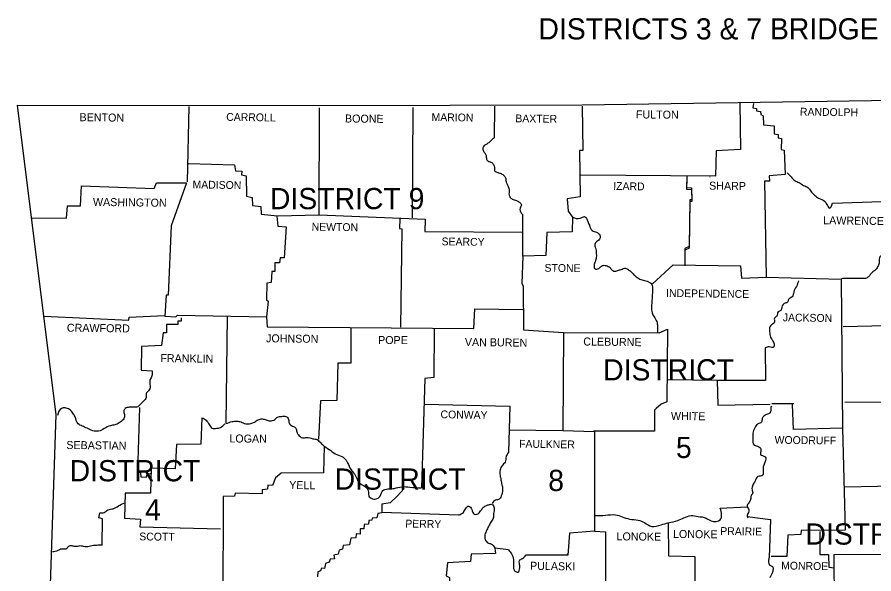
# Model space of a CAD drawing. Extents: x -43543 to 34500, y -13675 to 11152.
# Drawn here: x 10765 to 15268, y 7833 to 10759 of the extents above; entities that cross this region are included whole.
import ezdxf

# ---------------------------------------------------------------- set-up
doc = ezdxf.new("R2010")
doc.units = 0
for name, color, linetype in [('1', 7, 'Continuous'), ('2', 7, 'Continuous'), ('3', 7, 'Continuous'), ('R_Border', 7, 'Continuous')]:
    doc.layers.add(name, color=color, linetype=linetype)

msp = doc.modelspace()

# ---------------------------------------------------------------- linework, layer by layer
at = {"layer": '1'}
msp.add_line((14731.5, 8728.9), (14848, 8728.9), dxfattribs=at)
for points in [[(10765.1, 10295.4), (12347.2, 10294.4), (13735.5, 10297.3), (15373.4, 10322.8), (16132.6, 10340.4)], [(10765.1, 10295.4), (10967.6, 8669.3), (10906.6, 6830.5)], [(11668.1, 10289.5), (11659.3, 9893.2)], [(11666.2, 9990.1), (11906.9, 9982.3), (11912.7, 9951), (11946, 9950), (11945, 9930.4), (11968.5, 9924.5), (11970.5, 9817.9), (12000.8, 9811.1), (12002.8, 9769), (12045.8, 9763.1), (12047.8, 9724), (12132.9, 9715.2), (12352, 9720.1), (12354, 10282.6)], [(12844.2, 10284.6), (12841.2, 9703.4)], [(13274.7, 10291.4), (13272.7, 10124.1)], [(13735.5, 10291.4), (13737.5, 10058.6), (13720.8, 10057.6), (13723.8, 9814), (13655.3, 9804.2), (13661.2, 9738.6), (13684.6, 9708.3), (13682.7, 9631), (13549.6, 9626.1), (13544.7, 9506.8), (13423.4, 9502.9), (13417.5, 9358), (13424.4, 9346.3), (13427.3, 9115.4), (13636.7, 9101.7), (13633.8, 8586.1), (13800.1, 8581.2), (13800.1, 8056.8), (13669, 8047), (13659.2, 7931.5), (13439.1, 7930.6)], [(14564.2, 10306.1), (14566.2, 10063.5), (14439, 10056.6), (14435.1, 9923.6), (13727.7, 9927.5)], [(14634.7, 10305.1), (14631.7, 10281.7), (14651.3, 10278.7), (14650.3, 10267), (14672.8, 10262.1), (14674.8, 10246.4), (14685.5, 10239.6), (14688.5, 10192.6), (14744.3, 10186.8), (14744.3, 10144.7), (14764.8, 10141.8), (14764.8, 10125.1), (14782.4, 10120.2), (14781.4, 10063.5), (14797.1, 10060.5), (14801, 9932.4), (14717.8, 9924.5), (14718.8, 9897.2), (14693.4, 9896.2), (14702.2, 9391.3), (15096.5, 9382.5), (15103.3, 8597.8), (14846, 8591), (14841.1, 8723.1)], [(14284.4, 9920.6), (14282.4, 9863.9), (14309.8, 9861.9), (14310.8, 9799.3), (14301, 9799.3), (14297.1, 9552.8), (14274.6, 9543), (14274.6, 9460.8)], [(14284.4, 9911.8), (14282.4, 9855.1), (14309.8, 9853.1), (14310.8, 9790.5), (14301, 9790.5), (14297.1, 9543.9), (14274.6, 9534.2), (14274.6, 9452)], [(14406.7, 9918.7), (14407.7, 9919.7)], [(10842.4, 9703.4), (11025.3, 9702.4), (11030.2, 9767), (11097.7, 9767), (11103.6, 9871.7), (11485.2, 9858), (11496.9, 9887.4), (11654.4, 9888.3), (11575.2, 9661.4), (11559.5, 9298.4), (11547.8, 9297.4), (11541.9, 9187.8), (11599.7, 9182.9), (11608.5, 9191.7), (12075.2, 9182.9), (12080, 9131.1)], [(15050.5, 9780.7), (15413.5, 9793.4)], [(12130.9, 9713.2), (12134.8, 9660.4), (12179.8, 9657.4), (12168.1, 9493.1), (12147.6, 9494), (12143.6, 9467.6), (12120.2, 9467.6), (12119.2, 9422.6), (12104.5, 9421.6), (12099.6, 9363.9), (12078.1, 9361), (12075.2, 9272.9), (12084.9, 9266.1), (12075.2, 9182.9)], [(12352, 9720.1), (12909.7, 9696.6), (12908.8, 9633), (13420.5, 9629.1)], [(12775.7, 9699.5), (12774.7, 9648.6), (12787.4, 9645.7), (12779.6, 9129.1)], [(13423.4, 9502.9), (13422.4, 9723)], [(14102.4, 9356.1), (14214, 9456.9), (14566.2, 9452), (14573, 9386.4), (14701.2, 9391.3)], [(15224.6, 9384.5), (15105.3, 9384.5), (15096.5, 9382.5)], [(10906.9, 9186.8), (11352.1, 9166.3), (11354.1, 9181.9), (11540, 9190.7)], [(11869.7, 9186.8), (11862.8, 8622.3)], [(12080, 9131.1), (13166.1, 9122.3), (13171, 9225), (13423.4, 9222.1)], [(13420.5, 9223), (13423.4, 9226)], [(11628, 9179), (11628, 9161.4), (11609.4, 9161.4), (11610.4, 9143.8), (11550.7, 9142.8), (11549.8, 9098.8), (11533.1, 9098.8), (11524.3, 9033.2), (11418.6, 9028.3), (11417.7, 8904.1), (11474.4, 8900.2)], [(16008.4, 9151.6), (15107.2, 9131.1)], [(12519.4, 9123.2), (12518.4, 8940.3), (12450.9, 8939.3), (12445, 8744.6), (12358.9, 8741.7), (12349.1, 8540.1)], [(12957.7, 9118.3), (12955.7, 8864), (12908.8, 8860), (12890.2, 8284.7)], [(13636.7, 9101.7), (14139.6, 9098.8), (14182.6, 9119.3), (14179.7, 8736.8), (14150.4, 8724), (14123.9, 8701.5), (14115.1, 8692.7), (14114.2, 8583.2), (13794.2, 8583.2)], [(14697.3, 9021.5), (14699.2, 8849.3), (14444.9, 8848.3), (14183.6, 8853.2)], [(14444.9, 8848.3), (14448.8, 8720.1), (14723.7, 8725)], [(15115.1, 8734.8), (15492.7, 8736.8), (15493.7, 8750.5), (15624.8, 8760.2), (15624.8, 8739.7), (16194.2, 8755.4)], [(11407.9, 8706.4), (11398.1, 8369.9), (11412.8, 8365.9), (11415.7, 8342.5), (11445.1, 8340.5), (11448, 8357.1), (11471.5, 8361.1)], [(12906.8, 8724), (13353.9, 8713.3), (13348.1, 8471.6)], [(14731.5, 8712.3), (14726.6, 8711.3)], [(11736.6, 8653.6), (11729.8, 8513.7), (11602.6, 8512.7), (11595.7, 8385.5), (11469.5, 8388.4), (11465.6, 8257.3), (11333.5, 8256.4), (11329.6, 8125.3), (11412.8, 8120.4), (11409.8, 8080.2), (11834.5, 8068.5)], [(13349, 8590), (13633.8, 8586.1)], [(15103.3, 8597.8), (15118, 8061.7), (14885.1, 8060.7), (14884.2, 8039.2), (14816.7, 8035.2), (14810.8, 7923.7), (14728.6, 7923.7)], [(12379.4, 8503.9), (12375.5, 8363), (12152.5, 8362), (12123.1, 8336.6), (12106.5, 8297.5), (12082, 8299.4), (12081, 8276.9), (12052.7, 8274), (12053.6, 8253.4), (11911.8, 8257.3), (11906.9, 8241.7), (11848.2, 8239.7), (11846.2, 7667.4), (11797.3, 7666.4), (11801.2, 7637), (11754.2, 7638), (11753.3, 7616.5), (11707.3, 7616.5), (11708.3, 7600.8), (11639.8, 7598.9), (11638.8, 7539.2), (11572.3, 7545.1), (11561.5, 7063.7)], [(15115.1, 8289.6), (15891.9, 8305.3)], [(12799.2, 8280.8), (12764, 8242.7), (12725.8, 8206.5), (12681.8, 8199.6), (12681.8, 8153.6), (12660.2, 8150.7), (12656.3, 8127.2), (12631.9, 8125.3), (12629.9, 8114.5), (12613.3, 8113.5), (12612.3, 8093), (12588.8, 8092), (12586.9, 8068.5), (12567.3, 8068.5), (12568.3, 8041.1), (12546.7, 8043.1), (12545.8, 8021.5), (12519.4, 8019.6), (12511.5, 7984.4), (12478.3, 7981.4), (12475.3, 7961.9), (12457.7, 7957), (12452.8, 7936.4), (12430.3, 7931.5), (12432.3, 7911), (12409.8, 7909), (12405.9, 7893.4), (12385.3, 7887.5), (12380.4, 7861.1), (12364.8, 7862.1), (12359.9, 7848.4), (12345.2, 7843.5), (12344.2, 7817.1)], [(11211.2, 7983.4), (11214.2, 8121.3), (11194.6, 8127.2), (11200.5, 8153.6)], [(13085.9, 8141.9), (12682.7, 8154.6)], [(14460.5, 8178.1), (14602.4, 8184.9)], [(14602.4, 8134.1), (14724.7, 8118.4), (14717.8, 7918.8)], [(14186.6, 8101.8), (14188.5, 7926.6), (14326.5, 7923.7), (14327.4, 7548)], [(13800.1, 8056.8), (13856.8, 8052.9), (13857.8, 7679.1), (13806.9, 7466.8), (13915.5, 7461.9), (13914.6, 7281.9)], [(14984.9, 8055.8), (14984, 7934.5), (15029, 7934.5), (15030.9, 7867), (15059.3, 7864)], [(13347.1, 7958.9), (13276.6, 7966.8), (13279.6, 7940.3), (13151.4, 7935.4), (13147.5, 7897.3), (13027.1, 7890.4), (13020.3, 7822), (13037.9, 7813.1), (13037.9, 7768.1)], [(13654.3, 7932.5), (13659.2, 7937.4)], [(15115.1, 7066.6), (15191.4, 7071.5), (15190.4, 7270.1), (15119, 7275), (15122.9, 7663.4), (15061.3, 7672.3), (15059.3, 7933.5), (15893.9, 7939.4)]]:
    msp.add_lwpolyline(points, dxfattribs=at)
for points in [[(13272.7, 10124.1), (13255.1, 10109.5), (13239.5, 10095.8), (13216, 10079.1), (13213, 10063.5), (13220.9, 10047.8), (13228.7, 10035.1), (13231.6, 10017.5), (13238.5, 10002.8), (13255.1, 9996.9), (13268.8, 9984.2), (13273.7, 9966.6), (13275.7, 9950), (13291.3, 9942.2), (13308.9, 9936.3), (13325.6, 9924.5), (13333.4, 9909.9), (13335.3, 9891.3), (13342.2, 9876.6), (13350, 9859), (13352, 9844.3), (13350, 9829.6), (13353.9, 9815.9), (13366.7, 9802.2), (13389.2, 9795.4), (13404.8, 9785.6), (13415.6, 9771.9), (13408.7, 9755.3), (13409.7, 9740.6), (13418.5, 9723)], [(14811.8, 9941.2), (14833.3, 9918.7), (14851.9, 9900.1), (14873.4, 9889.3), (14898.8, 9874.6), (14921.3, 9862.9), (14936, 9844.3), (14956.6, 9823.8), (14977.1, 9807.1), (15009.4, 9791.5), (15020.2, 9774.9), (15034.8, 9754.3), (15050.5, 9780.7)], [(15410.5, 9792.5), (15395.9, 9769), (15384.1, 9741.6), (15360.6, 9710.3), (15343, 9679.9), (15340.1, 9659.4), (15326.4, 9632), (15318.6, 9604.6), (15309.8, 9581.1), (15309.8, 9556.7), (15316.6, 9532.2), (15314.7, 9509.7), (15300, 9498.9), (15296.1, 9470.6), (15290.2, 9451), (15277.5, 9431.4), (15258.9, 9416.8), (15239.3, 9394.2), (15224.6, 9384.5)], [(13684.6, 9708.3), (13723.8, 9701.5), (13747.3, 9710.3), (13763.9, 9684.8), (13772.7, 9665.3), (13787.4, 9636.9), (13810.9, 9628.1), (13828.5, 9612.4), (13828.5, 9595.8), (13812.8, 9580.1), (13801.1, 9564.5), (13805, 9545.9), (13808.9, 9520.5), (13808.9, 9496), (13803, 9473.5), (13798.1, 9453), (13803, 9435.3), (13821.6, 9438.3), (13841.2, 9453), (13861.7, 9453), (13881.3, 9442.2), (13901.8, 9423.6), (13922.4, 9427.5), (13939, 9432.4), (13962.5, 9439.3), (13979.1, 9430.5), (13993.8, 9418.7), (14011.4, 9400.1), (14028.1, 9388.4), (14049.6, 9377.6), (14076, 9370.8), (14100.5, 9354.1), (14104.4, 9325.8), (14103.4, 9301.3), (14101.4, 9271), (14099.5, 9237.7), (14102.4, 9205.4), (14113.2, 9183.9), (14126.9, 9158.5), (14130.8, 9135), (14129.8, 9097.8)], [(14872.4, 9373.7), (14860.7, 9343.4), (14847, 9314), (14838.2, 9288.6), (14819.6, 9273.9), (14813.7, 9260.2), (14797.1, 9254.3), (14784.4, 9234.8), (14778.5, 9217.2), (14764.8, 9209.3), (14757.9, 9187.8), (14745.2, 9176.1), (14746.2, 9156.5), (14731.5, 9142.8), (14719.8, 9127.1), (14719.8, 9105.6), (14724.7, 9077.2), (14734.5, 9060.6), (14743.3, 9039.1), (14742.3, 9025.4), (14717.8, 9025.4), (14697.3, 9021.5)], [(11474.4, 8900.2), (11474.4, 8879.6), (11466.6, 8858.1), (11461.7, 8839.5), (11464.6, 8815), (11455.8, 8795.5), (11443.1, 8779.8), (11443.1, 8760.2), (11428.4, 8739.7), (11412.8, 8724), (11399.1, 8711.3), (11374.6, 8709.4), (11354.1, 8708.4), (11333.5, 8701.5), (11325.7, 8686.9), (11329.6, 8664.4), (11321.8, 8642.8), (11301.2, 8626.2), (11278.7, 8615.4), (11255.3, 8611.5), (11223, 8595.9), (11193.6, 8583.2), (11162.3, 8585.1), (11133, 8597.8), (11106.5, 8609.6), (11086, 8621.3), (11069.4, 8657.5), (11058.6, 8677.1), (11040, 8696.6), (11017.5, 8704.5), (10998.9, 8702.5), (10976.4, 8664.4)], [(14726.6, 8711.3), (14721.7, 8679), (14703.2, 8670.2), (14681.6, 8648.7), (14676.7, 8629.1), (14659.1, 8621.3), (14642.5, 8600.8), (14631.7, 8572.4), (14631.7, 8543), (14638.6, 8509.8), (14663, 8501), (14674.8, 8481.4), (14672.8, 8460.8), (14696.3, 8447.2), (14700.2, 8435.4), (14696.3, 8422.7), (14685.5, 8386.5), (14686.5, 8362), (14684.6, 8351.3), (14658.2, 8344.4), (14642.5, 8318), (14631.7, 8299.4), (14627.8, 8275), (14630.8, 8257.3), (14622.9, 8243.6), (14620, 8223.1), (14610.2, 8205.5), (14601.4, 8188.9), (14611.2, 8169.3), (14608.3, 8155.6), (14602.4, 8134.1), (14607.3, 8127.2)], [(11736.6, 8653.6), (11758.2, 8639.9), (11774.8, 8617.4), (11789.5, 8598.8), (11813.9, 8597.8), (11833.5, 8601.7), (11856, 8621.3)], [(11862.8, 8622.3), (11895.1, 8633), (11918.6, 8635), (11942.1, 8631.1), (11966.6, 8621.3), (11993, 8623.3), (12012.5, 8630.1), (12032.1, 8642.8), (12053.6, 8646.7), (12074.2, 8642.8), (12095.7, 8637), (12119.2, 8643.8), (12132.9, 8656.5), (12156.4, 8660.4), (12176.9, 8660.4), (12191.6, 8643.8), (12194.5, 8626.2), (12213.1, 8609.6), (12229.7, 8598.8), (12234.6, 8578.3), (12243.4, 8563.6), (12252.2, 8553.8), (12265, 8547.9), (12286.5, 8549.9), (12319.8, 8543), (12341.3, 8538.1), (12360.9, 8521.5), (12379.4, 8503.9)], [(12379.4, 8503.9), (12413.7, 8480.4), (12446, 8459.9), (12479.2, 8445.2), (12497.8, 8423.7), (12514.5, 8390.4), (12528.2, 8369.9), (12545.8, 8344.4), (12558.5, 8316), (12579, 8300.4), (12600.6, 8286.7), (12611.3, 8262.2), (12616.2, 8237.8), (12639.7, 8226), (12662.2, 8230.9), (12674.9, 8245.6), (12686.7, 8271), (12713.1, 8278.9), (12747.3, 8281.8), (12786.5, 8290.6), (12829.5, 8288.7), (12890.2, 8284.7)], [(13348.1, 8471.6), (13335.3, 8449.1), (13329.5, 8419.8), (13313.8, 8401.2), (13304, 8379.6), (13303.1, 8351.3), (13307.9, 8325.8), (13312.8, 8301.4), (13316.8, 8278.9), (13311.9, 8250.5), (13299.1, 8226), (13279.6, 8219.2), (13261, 8202.6)], [(11200.5, 8153.6), (11222, 8155.6), (11242.5, 8169.3), (11269.9, 8175.2), (11297.3, 8189.8), (11331.6, 8205.5)], [(13085.9, 8141.9), (13110.3, 8155.6), (13123, 8176.1), (13138.7, 8188.9), (13154.3, 8171.2), (13168, 8145.8), (13182.7, 8145.8), (13201.3, 8163.4), (13213, 8179.1), (13227.7, 8190.8), (13243.4, 8195.7), (13260, 8197.7), (13272.7, 8179.1), (13268.8, 8149.7), (13268.8, 8130.1), (13258.1, 8109.6), (13246.3, 8088.1), (13233.6, 8063.6), (13223.8, 8037.2), (13225.8, 8011.8), (13239.5, 7995.1), (13255.1, 7990.2), (13276.6, 7968.7)], [(13802, 8139), (13856.8, 8140.9), (13910.6, 8142.9), (13944.9, 8133.1), (13984, 8120.4), (14030, 8114.5), (14062.3, 8101.8), (14100.5, 8082.2), (14149.4, 8091), (14187.5, 8100.8), (14237.4, 8113.5), (14269.7, 8127.2), (14306.9, 8139), (14344.1, 8134.1), (14386.2, 8126.2), (14412.6, 8110.6), (14460.5, 8117.4), (14460.5, 8178.1)], [(11211.2, 7983.4), (11182.9, 7982.4), (11150.6, 7978.5), (11121.2, 7974.6), (11094.8, 7979.5), (11070.3, 7975.6), (11053.7, 7979.5), (11033.2, 7974.6), (11021.4, 7962.8), (10997, 7962.8), (10979.3, 7955), (10951, 7948.2)], [(13347.1, 7958.9), (13363.7, 7937.4), (13373.5, 7908), (13373.5, 7874.8), (13381.3, 7847.4), (13397, 7841.5), (13406.8, 7865), (13404.8, 7888.5), (13404.8, 7902.2), (13421.4, 7913.9), (13439.1, 7930.6)], [(14717.8, 7918.8), (14713.9, 7899.2), (14721.7, 7878.7), (14735.4, 7871.8), (14737.4, 7852.3), (14732.5, 7832.7), (14728.6, 7824.9), (14719.8, 7813.1)]]:
    msp.add_spline(points, degree=3, dxfattribs=at)

# ---------------------------------------------------------------- texts
at = {"layer": '2'}
for s, height, rotation, p in [('FULTON', 42.06, 359.4996, (14017.3, 10226.9)), ('RANDOLPH', 41.09, 359.2583, (14879.3, 10241.6)), ('BENTON', 42.07, 359.2527, (11092.8, 10212.2)), ('CARROLL', 41.09, 359.1481, (11863.8, 10214.2)), ('BOONE', 42.07, 359.4001, (12488, 10205.3)), ('MARION', 41.09, 359.1854, (12943, 10213.2)), ('BAXTER', 41.09, 359.2559, (13383.3, 10206.3)), ('MADISON', 41.09, 359.0906, (11686.7, 9859)), ('IZARD', 41.08, 358.9258, (13897.9, 9851.2)), ('SHARP', 42.06, 359.3905, (14401.8, 9852.1)), ('WASHINGTON', 42.06, 359.232, (11163.3, 9767)), ('LAWRENCE', 42.07, 359.2678, (15001.6, 9670.2)), ('NEWTON', 41.09, 359.2717, (12312.9, 9636.9)), ('SEARCY', 41.08, 359.2527, (12995.8, 9559.6)), ('STONE', 41.08, 359.4001, (13536.9, 9420.7)), ('INDEPENDENCE', 41.081, 359.2187, (14175.8, 9288.6)), ('JACKSON', 41.08, 359.1352, (14789.3, 9160.4)), ('CRAWFORD', 42.06, 359.2771, (11026.3, 9105.6)), ('JOHNSON', 42.07, 359.3514, (12073.2, 9049.9)), ('POPE', 42.07, 359.6155, (12662.2, 9041)), ('VAN BUREN', 42.07, 359.3508, (13118.1, 9030.3)), ('CLEBURNE', 42.06, 359.2535, (13740.4, 9033.2)), ('FRANKLIN', 42.07, 359.1815, (11517.5, 8946.1)), ('CONWAY', 41.08, 359.0371, (12990, 8650.7)), ('WHITE', 42.07, 359.3139, (14201.2, 8641.9)), ('LOGAN', 42.07, 359.3969, (11880.5, 8523.5)), ('WOODRUFF', 41.08, 359.2748, (14746.2, 8516.6)), ('SEBASTIAN', 42.06, 359.2816, (11023.4, 8489.2)), ('FAULKNER', 41.09, 359.2486, (13402.9, 8496.1)), ('YELL', 42.07, 359.1987, (12194.5, 8278.9)), ('PERRY', 41.09, 359.0858, (12805, 8076.3)), ('LONOKE', 42.07, 359.4974, (14212, 8021.5)), ('PRAIRIE', 41.09, 359.2116, (14460.5, 8037.2)), ('SCOTT', 41.09, 359.4063, (11406.9, 8008.8)), ('LONOKE', 42.07, 359.4974, (13915.5, 8008.8)), ('PULASKI', 42.07, 359.053, (13460.6, 7854.2)), ('MONROE', 41.08, 359.0331, (14780.5, 7856.2))]:
    msp.add_text(s, height=height, rotation=rotation, dxfattribs=at).set_placement(p)
at = {"layer": '3'}
for s, height, p in [('DISTRICT 9', 111.54, (12093.7, 9749.4)), ('DISTRICT', 111.54, (13845.1, 8849.3)), ('5', 111.5, (14227.7, 8441.3)), ('DISTRICT', 111.54, (11041, 8319)), ('DISTRICT', 111.54, (12434.2, 8275)), ('8', 111.5, (13556.5, 8268.1)), ('4', 111.5, (11437.2, 8113.5)), ('DISTRICT', 111.54, (14908.6, 7986.3))]:
    msp.add_text(s, height=height, dxfattribs=at).set_placement(p)
at = {"layer": 'R_Border'}
msp.add_text('DISTRICTS 3 & 7 BRIDGE PRESERVATION (2021) (S) ', height=111.378, dxfattribs=at).set_placement((13505.2, 10641.7))

doc.saveas('drawing.dxf')
